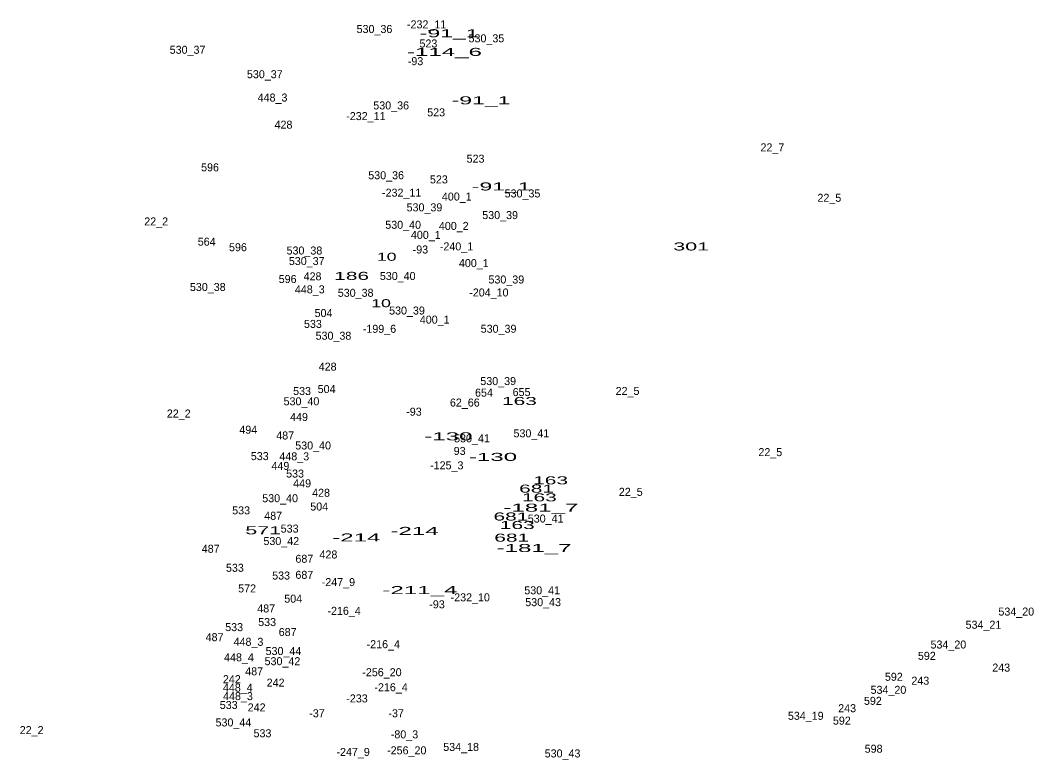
# Model space of a CAD drawing. Extents: x -661742 to -657295, y -1002932 to -996888.
# Drawn here: x -659827 to -659321, y -999465 to -999095 of the extents above; entities that cross this region are included whole.
import ezdxf
from ezdxf.enums import TextEntityAlignment as Align

# ---------------------------------------------------------------- set-up
doc = ezdxf.new("R2010")
doc.units = 0
doc.header["$LTSCALE"] = 1.6
doc.layers.add('24', color=7, linetype='Continuous')

msp = doc.modelspace()

# ---------------------------------------------------------------- texts
at = {"layer": '24'}
for s, p in [('530_36', (-659650.024, -999101.26)), ('-232_11', (-659623.969, -999098.94)), ('530_35', (-659594.109, -999105.92)), ('530_37', (-659743.394, -999111.64)), ('523', (-659623.087, -999108.5)), ('-93', (-659629.51, -999117.34)), ('530_37', (-659704.814, -999123.86)), ('448_3', (-659700.954, -999135.53)), ('530_36', (-659641.684, -999139.46)), ('-232_11', (-659654.329, -999144.81)), ('523', (-659619.217, -999142.93)), ('428', (-659695.471, -999149.09)), ('22_7', (-659451.24, -999160.44)), ('523', (-659599.537, -999166.09)), ('596', (-659732.178, -999170.41)), ('530_36', (-659644.204, -999174.37)), ('523', (-659617.857, -999176.45)), ('-232_11', (-659636.439, -999183.08)), ('400_1', (-659608.921, -999185.03)), ('530_35', (-659576.079, -999183.47)), ('22_5', (-659422.785, -999185.65)), ('530_39', (-659625.064, -999190.43)), ('22_2', (-659759.075, -999197.47)), ('530_39', (-659587.254, -999194.3)), ('530_40', (-659635.697, -999199.15)), ('400_2', (-659610.417, -999199.71)), ('564', (-659733.837, -999207.58)), ('400_1', (-659624.391, -999204.19)), ('596', (-659718.218, -999210.36)), ('530_38', (-659685.019, -999212.01)), ('-93', (-659627.09, -999211.5)), ('-240_1', (-659609.044, -999209.95)), ('530_37', (-659683.874, -999217.28)), ('400_1', (-659600.411, -999218.31)), ('596', (-659693.408, -999226.26)), ('428', (-659680.961, -999224.93)), ('530_40', (-659638.417, -999224.75)), ('530_39', (-659584.154, -999226.5)), ('530_38', (-659733.299, -999230.24)), ('448_3', (-659682.344, -999231.41)), ('530_38', (-659659.429, -999233.15)), ('-204_10', (-659592.867, -999232.99)), ('504', (-659675.485, -999243.27)), ('530_39', (-659633.784, -999242.02)), ('533', (-659680.777, -999248.71)), ('400_1', (-659619.941, -999246.56)), ('-199_6', (-659647.532, -999251.16)), ('530_39', (-659588.034, -999251.13)), ('530_38', (-659670.519, -999254.61)), ('428', (-659673.421, -999270.07)), ('530_39', (-659588.224, -999277.29)), ('533', (-659686.207, -999282.26)), ('504', (-659673.935, -999281.29)), ('654', (-659595.327, -999283.06)), ('655', (-659576.553, -999282.79)), ('22_5', (-659523.615, -999282.23)), ('530_40', (-659686.497, -999287.4)), ('62_66', (-659604.901, -999288.03)), ('22_2', (-659747.805, -999293.51)), ('-93', (-659630.31, -999292.6)), ('449', (-659687.721, -999295.24)), ('494', (-659713.081, -999301.6)), ('487', (-659694.627, -999304.5)), ('530_41', (-659571.647, -999303.41)), ('530_40', (-659680.677, -999309.49)), ('530_41', (-659601.317, -999305.93)), ('93', (-659607.483, -999312.22)), ('22_5', (-659452.285, -999312.82)), ('533', (-659707.337, -999314.81)), ('449', (-659697.021, -999319.68)), ('448_3', (-659690.094, -999314.93)), ('-125_3', (-659613.916, -999319.42)), ('533', (-659689.697, -999323.54)), ('449', (-659686.161, -999328.41)), ('428', (-659676.711, -999333.14)), ('22_5', (-659522.005, -999332.67)), ('530_40', (-659697.157, -999335.86)), ('533', (-659716.647, -999341.94)), ('487', (-659700.637, -999344.64)), ('504', (-659677.625, -999340.02)), ('530_41', (-659564.517, -999346.03)), ('533', (-659692.407, -999351.05)), ('530_42', (-659696.574, -999357.28)), ('487', (-659731.847, -999361.13)), ('428', (-659673.031, -999364)), ('687', (-659685.058, -999366.14)), ('533', (-659719.747, -999370.64)), ('533', (-659696.677, -999374.52)), ('687', (-659685.058, -999374.17)), ('-247_9', (-659668.048, -999377.8)), ('572', (-659713.663, -999380.96)), ('-232_10', (-659602.169, -999385.42)), ('530_41', (-659566.257, -999381.91)), ('504', (-659690.615, -999386.07)), ('-93', (-659618.78, -999388.91)), ('530_43', (-659565.774, -999387.83)), ('487', (-659704.127, -999390.99)), ('-216_4', (-659665.196, -999392.17)), ('534_20', (-659329.414, -999392.53)), ('533', (-659720.137, -999400.31)), ('533', (-659703.657, -999397.79)), ('534_21', (-659345.813, -999399.12)), ('487', (-659729.907, -999405.34)), ('687', (-659693.398, -999402.77)), ('448_3', (-659712.974, -999407.66)), ('-216_4', (-659645.616, -999408.85)), ('534_20', (-659363.334, -999409.01)), ('448_4', (-659717.718, -999415.42)), ('530_44', (-659695.488, -999412.26)), ('592', (-659374.103, -999414.67)), ('530_42', (-659695.994, -999417.35)), ('243', (-659336.941, -999420.54)), ('487', (-659710.127, -999422.41)), ('-256_20', (-659646.281, -999422.87)), ('592', (-659390.583, -999425.14)), ('448_4', (-659718.298, -999430.55)), ('242', (-659721.271, -999426.34)), ('242', (-659699.421, -999428.08)), ('-216_4', (-659641.736, -999430.37)), ('243', (-659377.361, -999427.11)), ('448_3', (-659718.204, -999434.81)), ('-233', (-659658.755, -999435.96)), ('534_20', (-659393.274, -999431.66)), ('533', (-659722.847, -999439.24)), ('242', (-659708.891, -999440.46)), ('243', (-659413.911, -999440.85)), ('592', (-659401.053, -999437.17)), ('-37', (-659678.751, -999443.39)), ('-37', (-659639.201, -999443.39)), ('534_19', (-659434.588, -999444.65)), ('530_44', (-659720.498, -999447.96)), ('592', (-659416.563, -999447.06)), ('22_2', (-659821.285, -999451.8)), ('533', (-659705.977, -999453.38)), ('-80_3', (-659635.036, -999453.93)), ('534_18', (-659606.743, -999460.21)), ('598', (-659400.683, -999461.11)), ('-247_9', (-659660.698, -999462.73)), ('-256_20', (-659633.901, -999461.92)), ('530_43', (-659556.074, -999463.47))]:
    msp.add_text(s, height=4, dxfattribs=at).set_placement(p, align=Align.CENTER)
for s, width, p in [('-91_1', 2.15, (-659612.693, -999103.37)), ('-114_6', 2.25, (-659615.058, -999112.7)), ('-91_1', 2.15, (-659596.803, -999136.92)), ('-91_1', 2.15, (-659586.713, -999179.98)), ('301', 2, (-659491.824, -999209.99)), ('10', 1.65, (-659643.914, -999215.13)), ('186', 1.95, (-659661.423, -999224.69)), ('10', 1.65, (-659646.724, -999238.35)), ('163', 1.95, (-659577.613, -999287.25)), ('-130', 2.25, (-659613.107, -999304.92)), ('-130', 2.25, (-659590.817, -999315.2)), ('163', 1.95, (-659562.043, -999326.92)), ('681', 1.95, (-659569.053, -999331.05)), ('163', 1.95, (-659567.653, -999335.42)), ('681', 1.95, (-659581.853, -999345.01)), ('-181_7', 2.25, (-659566.893, -999340.58)), ('163', 1.95, (-659578.683, -999349.25)), ('571', 2, (-659705.603, -999351.9)), ('-214', 2.25, (-659630.006, -999352.21)), ('-214', 2.25, (-659659.086, -999355.5)), ('681', 1.95, (-659581.463, -999355.58)), ('-181_7', 2.25, (-659570.283, -999360.75)), ('-211_4', 2.25, (-659627.323, -999381.81))]:
    msp.add_text(s, height=4, dxfattribs=dict(at, width=width)).set_placement(p, align=Align.CENTER)

doc.saveas('drawing.dxf')
